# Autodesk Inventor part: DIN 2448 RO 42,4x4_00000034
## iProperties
Created: 2006-02
Part Number: DIN 2448 RO 42,4x4_00000034
Material: Default
Document SubType Name: Modeling
Designer: FranzK
Stock Number: DIN 2448 RO 42,4x4
Mass: 1862.64 g
Surface Area: 9322.84 cm^2
Volume: 1862.64 cm^3
Density: 1 g/cm^3
G_L: 3860.000 mm
G_W: 42.400 mm
G_H: 42.400 mm
AFG_Item: 42.4 x 4
CSToolsMass: 2.0
CSToolsVolume: 1862638.0
CSToolsArea: 9323.0
Author: FranzK
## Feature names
1. AFG_Detailed_DIN 2448 RO 42,4x4_00000034 [Extrusion]
2. AFG_Simplified_DIN 2448 RO 42,4x4_00000034 [Extrusion]
